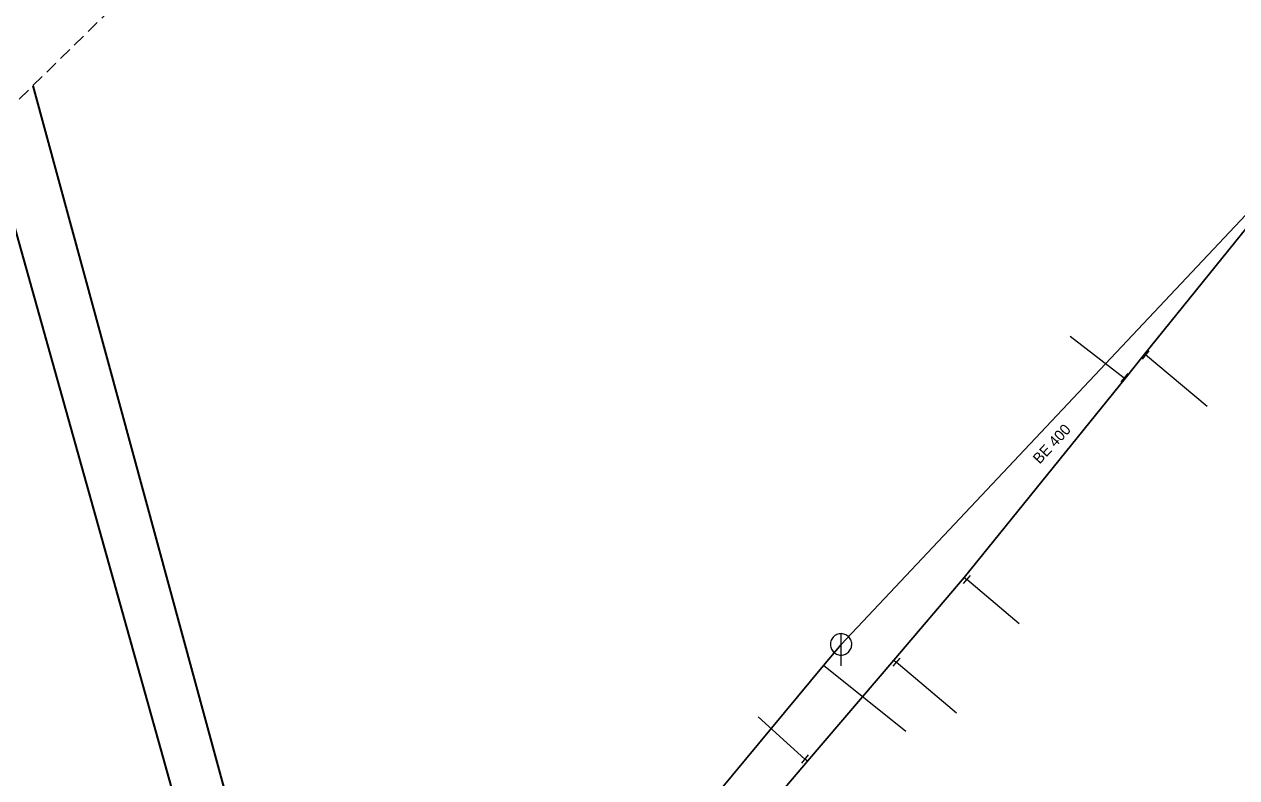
# Model space of a CAD drawing. Extents: x -779496 to -779026, y -977086 to -976624.
# Drawn here: x -779315.3 to -779202.2, y -976856.2 to -976785.8 of the extents above; entities that cross this region are included whole.
import ezdxf

# ---------------------------------------------------------------- set-up
doc = ezdxf.new("R2010")
doc.units = 0
doc.header["$LTSCALE"] = 0.4
doc.linetypes.add('MEDIUM_DASHED', pattern=[4.5, 3, -1.5])
for name, color, linetype, lineweight in [('1', 7, 'MEDIUM_DASHED', 25), ('11', 7, 'Continuous', 13), ('13', 7, 'Continuous', 13), ('14', 7, 'Continuous', 13), ('17', 7, 'Continuous', 25), ('22', 7, 'Continuous', 13), ('34', 7, 'Continuous', 13)]:
    doc.layers.add(name, color=color, linetype=linetype, lineweight=lineweight)

msp = doc.modelspace()

# ---------------------------------------------------------------- linework, layer by layer
at = {"layer": '1'}
msp.add_lwpolyline([(-779144.045, -976624.23), (-779025.876, -976692.559), (-779211.57, -976955.425), (-779456.75, -977086.455), (-779496.14, -976963.463), (-779320.896, -976797.866)], close=True, dxfattribs=at)
at = {"layer": '11'}
msp.add_line((-779233.054, -976851.829), (-779240.711, -976845.665), dxfattribs=at)
at = {"layer": '13'}
for p, q in [((-779217.693, -976814.954), (-779212.657, -976818.822)), ((-779204.918, -976821.517), (-779210.682, -976816.69)), ((-779222.458, -976841.798), (-779227.356, -976837.645)), ((-779228.323, -976850.128), (-779233.936, -976845.368)), ((-779246.82, -976850.465), (-779242.461, -976854.404))]:
    msp.add_line(p, q, dxfattribs=at)
at = {"layer": '14'}
for p, q in [((-779210.76, -976816.627), (-779210.682, -976816.69)), ((-779212.579, -976818.883), (-779212.657, -976818.822)), ((-779227.585, -976837.452), (-779227.356, -976837.645)), ((-779234.164, -976845.175), (-779233.936, -976845.368)), ((-779242.228, -976854.603), (-779242.461, -976854.404))]:
    msp.add_line(p, q, dxfattribs=at)
at = {"layer": '14', "lineweight": 25}
msp.add_lwpolyline([(-779187.41, -976790.809), (-779190.807, -976793.919), (-779200.812, -976803.077), (-779239.083, -976843.704), (-779240.711, -976845.665), (-779251.651, -976858.85), (-779257.611, -976867.208)], dxfattribs=at)
at = {"layer": '17'}
msp.add_lwpolyline([(-779276.545, -976891.073), (-779272.473, -976886.943), (-779252.653, -976866.844), (-779246.603, -976859.784), (-779242.228, -976854.603), (-779234.164, -976845.175), (-779227.585, -976837.452), (-779212.579, -976818.883), (-779210.76, -976816.627), (-779191.487, -976792.772), (-779191.372, -976792.629), (-779190.682, -976791.787), (-779189.552, -976790.451), (-779187.15, -976792.396)], dxfattribs=at)
at = {"layer": '17', "lineweight": 35}
for points in [[(-779314.495, -976791.582), (-779291.37, -976876.552), (-779283.847, -976885.578)], [(-779318.746, -976795.755), (-779298.18, -976869.129), (-779294.52, -976873.809)]]:
    msp.add_lwpolyline(points, dxfattribs=at)
at = {"layer": '22'}
msp.add_line((-779239.083, -976845.704), (-779239.082, -976842.704), dxfattribs=at)
msp.add_lwpolyline([(-779238.083, -976843.704), (-779238.088, -976843.595), (-779238.106, -976843.487), (-779238.136, -976843.381), (-779238.176, -976843.28), (-779238.228, -976843.183), (-779238.29, -976843.093), (-779238.362, -976843.01), (-779238.442, -976842.936), (-779238.53, -976842.87), (-779238.624, -976842.815), (-779238.724, -976842.77), (-779238.829, -976842.737), (-779238.936, -976842.715), (-779239.045, -976842.705), (-779239.155, -976842.707), (-779239.263, -976842.721), (-779239.37, -976842.746), (-779239.473, -976842.783), (-779239.571, -976842.832), (-779239.663, -976842.89), (-779239.749, -976842.959), (-779239.826, -976843.036), (-779239.895, -976843.122), (-779239.954, -976843.214), (-779240.002, -976843.312), (-779240.039, -976843.415), (-779240.065, -976843.522), (-779240.079, -976843.63), (-779240.082, -976843.74), (-779240.072, -976843.849), (-779240.051, -976843.956), (-779240.017, -976844.06), (-779239.973, -976844.16), (-779239.918, -976844.255), (-779239.852, -976844.343), (-779239.778, -976844.423), (-779239.695, -976844.495), (-779239.605, -976844.557), (-779239.509, -976844.609), (-779239.407, -976844.65), (-779239.302, -976844.68), (-779239.194, -976844.698), (-779239.084, -976844.704), (-779238.975, -976844.698), (-779238.867, -976844.68), (-779238.762, -976844.651), (-779238.66, -976844.61), (-779238.563, -976844.558), (-779238.473, -976844.496), (-779238.39, -976844.425), (-779238.315, -976844.345), (-779238.25, -976844.257), (-779238.194, -976844.163), (-779238.15, -976844.063), (-779238.116, -976843.959), (-779238.094, -976843.851), (-779238.084, -976843.742)], close=True, dxfattribs=at)
at = {"layer": '34'}
for p, q in [((-779210.368, -976816.3), (-779210.995, -976817.079)), ((-779212.34, -976818.434), (-779212.974, -976819.208)), ((-779227.032, -976837.263), (-779227.68, -976838.025)), ((-779233.611, -976844.987), (-779234.261, -976845.747)), ((-779242.138, -976854.021), (-779242.784, -976854.785))]:
    msp.add_line(p, q, dxfattribs=at)

# ---------------------------------------------------------------- texts
at = {"layer": '1'}
msp.add_text('BE 400', height=1, rotation=47, dxfattribs=at).set_placement((-779220.559, -976826.935))

doc.saveas('drawing.dxf')
